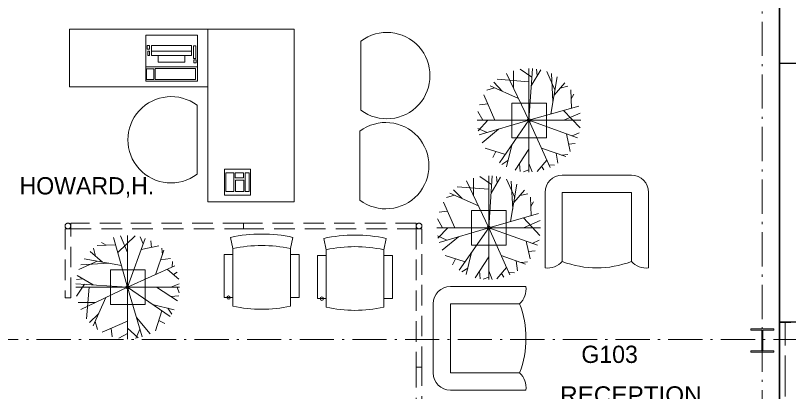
# Model space of a CAD drawing. Extents: x -118748 to -117136, y -118748 to -117596.
# Drawn here: x -117681.9 to -117467, y -118199.3 to -118094.8 of the extents above; entities that cross this region are included whole.
import ezdxf
from ezdxf.enums import TextEntityAlignment as Align

# ---------------------------------------------------------------- set-up
doc = ezdxf.new("R2010")
doc.units = 0
doc.header["$LTSCALE"] = 1.9
doc.header["$PDMODE"] = 32
doc.header["$PDSIZE"] = 0.95
for name, pattern in [('DOT_DASHED', [7.7, 5, -1.2, 0.3, -1.2]), ('LONG_DASHED', [7.5, 6, -1.5]), ('MEDIUM_DASHED', [4.5, 3, -1.5])]:
    doc.linetypes.add(name, pattern=pattern)
for name, color, linetype, lineweight in [('10', 7, 'DOT_DASHED', 13), ('12', 7, 'Continuous', 13), ('15', 7, 'Continuous', 13), ('16', 7, 'Continuous', 13), ('20', 7, 'MEDIUM_DASHED', 13), ('23', 7, 'Continuous', 25), ('30', 7, 'Continuous', 13), ('4', 7, 'Continuous', 35), ('5', 7, 'Continuous', 13), ('6', 7, 'Continuous', 13), ('60', 7, 'LONG_DASHED', 13), ('9', 7, 'Continuous', 35)]:
    doc.layers.add(name, color=color, linetype=linetype, lineweight=lineweight)
doc.layers.add('53', color=7, linetype='Continuous')

msp = doc.modelspace()

# ---------------------------------------------------------------- linework, layer by layer
at = {"layer": '10'}
for p, q in [((-117474.321, -117628.339), (-117474.321, -118698.41)), ((-118641.571, -118184.81), (-117285.521, -118184.81))]:
    msp.add_line(p, q, dxfattribs=at)
at = {"layer": '12'}
msp.add_lwpolyline([(-117477.504, -118188.362), (-117471.088, -118188.362), (-117471.088, -118187.966), (-117474.172, -118187.966), (-117474.172, -118182.262), (-117471.088, -118182.262), (-117471.088, -118181.866), (-117477.504, -118181.866), (-117477.504, -118182.262), (-117474.42, -118182.262), (-117474.42, -118187.966), (-117477.504, -118187.966)], close=True, dxfattribs=at)
at = {"layer": '15'}
for p, q in [((-117585.848, -118101.88), (-117585.848, -118121.08)), ((-117631.41, -118138.921), (-117631.41, -118119.721)), ((-117586.129, -118126.911), (-117586.129, -118146.111)), ((-117529.872, -118139.148), (-117510.672, -118139.148)), ((-117534.672, -118164.933), (-117534.672, -118143.948)), ((-117505.872, -118143.948), (-117505.872, -118164.933)), ((-117621.431, -118159.567), (-117622.107, -118156.439)), ((-117605.431, -118159.567), (-117604.755, -118156.439)), ((-117595.511, -118159.869), (-117596.187, -118156.741)), ((-117579.511, -118159.869), (-117578.835, -118156.741)), ((-117623.831, -118173.167), (-117623.831, -118161.167)), ((-117623.831, -118161.167), (-117621.431, -118161.167)), ((-117621.431, -118175.567), (-117621.431, -118159.567)), ((-117621.431, -118173.167), (-117621.431, -118161.167)), ((-117605.431, -118175.567), (-117605.431, -118159.567)), ((-117605.431, -118173.167), (-117605.431, -118161.167)), ((-117605.431, -118161.167), (-117603.031, -118161.167)), ((-117603.031, -118173.167), (-117603.031, -118161.167)), ((-117595.511, -118175.869), (-117595.511, -118159.869)), ((-117579.511, -118175.869), (-117579.511, -118159.869)), ((-117597.911, -118173.469), (-117597.911, -118161.469)), ((-117597.911, -118161.469), (-117595.511, -118161.469)), ((-117595.511, -118173.469), (-117595.511, -118161.469)), ((-117579.511, -118173.469), (-117579.511, -118161.469)), ((-117579.511, -118161.469), (-117577.111, -118161.469)), ((-117577.111, -118173.469), (-117577.111, -118161.469)), ((-117560.955, -118170.1), (-117539.969, -118170.1)), ((-117621.431, -118173.167), (-117623.831, -118173.167)), ((-117603.031, -118173.167), (-117605.431, -118173.167)), ((-117595.511, -118173.469), (-117597.911, -118173.469)), ((-117577.111, -118173.469), (-117579.511, -118173.469)), ((-117565.755, -118194.1), (-117565.755, -118174.899)), ((-117539.969, -118198.899), (-117560.955, -118198.899))]:
    msp.add_line(p, q, dxfattribs=at)
at = {"layer": '15', "lineweight": 25}
for p, q in [((-117469.521, -118108.01), (-117459.921, -118108.01)), ((-117469.521, -118180.01), (-117469.521, -118108.01)), ((-117379.921, -118180.01), (-117469.521, -118180.01))]:
    msp.add_line(p, q, dxfattribs=at)
at = {"layer": '15'}
for points in [[(-117628.41, -118114.556), (-117628.41, -118098.556), (-117666.81, -118098.556), (-117666.81, -118114.556)], [(-117604.41, -118146.556), (-117604.41, -118098.556), (-117628.41, -118098.556), (-117628.41, -118146.556)]]:
    msp.add_lwpolyline(points, close=True, dxfattribs=at)
for points in [[(-117529.872, -118163.148), (-117529.872, -118143.948), (-117510.672, -118143.948), (-117510.672, -118163.148)], [(-117541.755, -118194.1), (-117560.955, -118194.1), (-117560.955, -118174.899), (-117541.755, -118174.899)]]:
    msp.add_lwpolyline(points, dxfattribs=at)
for centre, radius, start, end in [((-117578.648, -118111.48), 12, 233.13011, 126.8699), ((-117638.61, -118129.321), 12, 53.1301, 306.8699), ((-117578.929, -118136.511), 12, 233.13011, 126.8699), ((-117529.872, -118143.948), 4.8, 90, 180), ((-117510.672, -118143.948), 4.8, 0, 90), ((-117613.431, -118196.575), 41.063, 77.80217, 102.19783), ((-117587.511, -118196.877), 41.063, 77.80217, 102.19783), ((-117613.431, -118196.575), 37.863, 77.80217, 102.19783), ((-117613.431, -118196.575), 37.863, 77.80217, 102.19783), ((-117587.511, -118196.877), 37.863, 77.80217, 102.19783), ((-117587.511, -118196.877), 37.863, 77.80217, 102.19783), ((-117533.977, -118159.456), 5.521, 262.77334, 318.03706), ((-117520.272, -118138.234), 26.699, 248.92678, 291.07322), ((-117506.566, -118159.456), 5.521, 221.96294, 277.22666), ((-117560.955, -118174.899), 4.8, 90, 180), ((-117545.447, -118170.794), 5.521, 311.96294, 7.22666), ((-117613.431, -118138.559), 37.863, 257.80217, 282.19782), ((-117587.511, -118138.86), 37.863, 257.80217, 282.19782), ((-117566.668, -118184.5), 26.699, 338.92678, 21.07322), ((-117560.955, -118194.1), 4.8, 180, 270), ((-117545.447, -118198.205), 5.521, 352.77334, 48.03706)]:
    msp.add_arc(centre, radius, start, end, dxfattribs=at)
for p in [(-117622.631, -118173.167), (-117596.711, -118173.469)]:
    msp.add_point(p, dxfattribs=at)
at = {"layer": '16'}
for p, q in [((-117469.521, -118108.01), (-117469.521, -118069.61)), ((-117631.259, -118109.006), (-117645.659, -118109.006))]:
    msp.add_line(p, q, dxfattribs=at)
for points in [[(-117631.259, -118113.006), (-117631.259, -118100.206), (-117645.659, -118100.206), (-117645.659, -118113.006)], [(-117644.657, -118103.104), (-117644.657, -118104.102), (-117645.239, -118104.102), (-117645.239, -118103.104)], [(-117632.924, -118104.685), (-117632.924, -118103.085), (-117644.033, -118103.085), (-117644.033, -118104.685)], [(-117631.717, -118106.724), (-117631.717, -118103.187), (-117632.424, -118103.187), (-117632.424, -118106.724)], [(-117644.657, -118104.685), (-117644.657, -118105.933), (-117645.073, -118105.933), (-117645.073, -118104.685)], [(-117632.924, -118105.891), (-117632.924, -118104.685), (-117644.033, -118104.685), (-117644.033, -118105.891)], [(-117634.837, -118107.764), (-117634.837, -118105.891), (-117642.16, -118105.891), (-117642.16, -118107.764)], [(-117631.634, -118107.972), (-117631.634, -118107.14), (-117632.299, -118107.14), (-117632.299, -118107.972)], [(-117643.408, -118109.636), (-117643.408, -118112.59), (-117645.406, -118112.59), (-117645.406, -118109.636)], [(-117631.8, -118109.553), (-117631.8, -118112.549), (-117642.992, -118112.549), (-117642.992, -118109.553)], [(-117616.563, -118144.712), (-117616.563, -118137.512), (-117623.763, -118137.512), (-117623.763, -118144.712)], [(-117621.182, -118138.547), (-117621.182, -118143.664), (-117623.387, -118143.664), (-117623.387, -118138.547)], [(-117618.519, -118138.464), (-117618.519, -118139.92), (-117620.807, -118139.92), (-117620.807, -118138.464)], [(-117618.02, -118143.706), (-117618.02, -118138.464), (-117616.938, -118138.464), (-117616.938, -118143.706)], [(-117618.436, -118140.585), (-117618.436, -118143.706), (-117620.724, -118143.706), (-117620.724, -118140.585)]]:
    msp.add_lwpolyline(points, close=True, dxfattribs=at)
at = {"layer": '20'}
for points in [[(-117618.495, -118154.079), (-117618.495, -118152.479), (-117666.495, -118152.479), (-117666.495, -118154.079)], [(-117570.495, -118154.079), (-117570.495, -118152.479), (-117618.495, -118152.479), (-117618.495, -118154.079)], [(-117666.495, -118154.079), (-117668.095, -118154.079), (-117668.095, -118173.279), (-117666.495, -118173.279)], [(-117570.495, -118192.479), (-117568.895, -118192.479), (-117568.895, -118154.079), (-117570.495, -118154.079)], [(-117570.495, -118240.479), (-117568.895, -118240.479), (-117568.895, -118192.479), (-117570.495, -118192.479)]]:
    msp.add_lwpolyline(points, close=True, dxfattribs=at)
for centre in [(-117667.295, -118153.279), (-117569.695, -118153.279)]:
    msp.add_circle(centre, 0.8, dxfattribs=at)
at = {"layer": '23'}
for p, q in [((-117469.521, -118180.01), (-117466.321, -118180.01)), ((-117469.521, -118292.01), (-117469.521, -118180.01))]:
    msp.add_line(p, q, dxfattribs=at)
at = {"layer": '30'}
for p, q in [((-117538.343, -118111.88), (-117541.613, -118109.705)), ((-117539.152, -118138.293), (-117539.152, -118109.493)), ((-117539.152, -118123.893), (-117538.184, -118109.526)), ((-117536.825, -118111.484), (-117536.998, -118109.655)), ((-117539.152, -118123.893), (-117545.335, -118110.888)), ((-117543.402, -118114.953), (-117543.399, -118110.134)), ((-117538.506, -118114.307), (-117535.866, -118109.873)), ((-117531.925, -118115.463), (-117534.189, -118110.375)), ((-117533.074, -118122.184), (-117531.303, -118111.82)), ((-117532.482, -118118.718), (-117532.899, -118110.921)), ((-117546.568, -118115.82), (-117548.935, -118113.326)), ((-117539.152, -118113.172), (-117547.947, -118112.491)), ((-117532.17, -118116.893), (-117529.212, -118113.474)), ((-117548.705, -118114.872), (-117550.877, -118115.533)), ((-117542.033, -118117.832), (-117549.921, -118114.333)), ((-117530.499, -118114.962), (-117528.293, -118114.436)), ((-117527.345, -118120.572), (-117527.528, -118115.393)), ((-117548.582, -118123.893), (-117551.677, -118116.788)), ((-117527.437, -118117.977), (-117526.695, -118116.668)), ((-117550.585, -118119.295), (-117552.903, -118119.62)), ((-117539.152, -118123.893), (-117525.29, -118119.994)), ((-117551.989, -118123.893), (-117553.344, -118121.455)), ((-117529.512, -118121.182), (-117524.912, -118126.036)), ((-117529.47, -118123.893), (-117524.892, -118121.892)), ((-117524.752, -118123.893), (-117553.552, -118123.893)), ((-117550.555, -118123.893), (-117553.255, -118126.801)), ((-117539.152, -118123.893), (-117552.96, -118127.979)), ((-117539.152, -118123.893), (-117547.332, -118135.744)), ((-117539.152, -118123.893), (-117533.25, -118137.028)), ((-117539.152, -118123.893), (-117525.605, -118128.777)), ((-117550.767, -118127.33), (-117553.375, -118126.144)), ((-117547.583, -118126.388), (-117552.117, -118130.158)), ((-117528.702, -118127.66), (-117527.667, -118132.579)), ((-117527.082, -118128.244), (-117525.173, -118127.352)), ((-117543.94, -118130.83), (-117545.402, -118136.866)), ((-117528.105, -118130.5), (-117526.272, -118130.333)), ((-117545.692, -118133.368), (-117551.302, -118131.622)), ((-117548.38, -118132.532), (-117549.209, -118134.198)), ((-117539.152, -118131.961), (-117542.944, -118137.785)), ((-117535.675, -118131.632), (-117528.898, -118134.004)), ((-117531.57, -118133.068), (-117531.148, -118135.864)), ((-117530.128, -118133.573), (-117528.328, -118133.391)), ((-117544.977, -118135.112), (-117546.639, -118136.194)), ((-117534.188, -118134.941), (-117536.871, -118138.111)), ((-117541.726, -118135.914), (-117541.548, -118138.092)), ((-117539.152, -118137.626), (-117540.667, -118138.213)), ((-117539.152, -118135.905), (-117538.215, -118138.263)), ((-117535.622, -118136.636), (-117534.991, -118137.679)), ((-117533.599, -118136.25), (-117532.015, -118136.4)), ((-117549.513, -118141.738), (-117552.783, -118139.563)), ((-117550.322, -118168.152), (-117550.322, -118139.352)), ((-117550.322, -118153.751), (-117549.354, -118139.384)), ((-117549.676, -118144.165), (-117547.036, -118139.731)), ((-117547.995, -118141.343), (-117548.168, -118139.514)), ((-117550.322, -118153.751), (-117556.505, -118140.746)), ((-117554.572, -118144.811), (-117554.569, -118139.992)), ((-117543.095, -118145.322), (-117545.359, -118140.234)), ((-117544.244, -118152.042), (-117542.473, -118141.679)), ((-117543.652, -118148.577), (-117544.069, -118140.78)), ((-117553.203, -118147.69), (-117561.091, -118144.191)), ((-117557.738, -118145.679), (-117560.105, -118143.185)), ((-117550.322, -118143.03), (-117559.117, -118142.35)), ((-117543.34, -118146.751), (-117540.382, -118143.333)), ((-117559.875, -118144.731), (-117562.047, -118145.392)), ((-117541.669, -118144.821), (-117539.463, -118144.295)), ((-117538.515, -118150.431), (-117538.698, -118145.252)), ((-117559.752, -118153.751), (-117562.847, -118146.647)), ((-117538.607, -118147.835), (-117537.865, -118146.527)), ((-117561.755, -118149.153), (-117564.073, -118149.479)), ((-117550.322, -118153.751), (-117536.46, -118149.853)), ((-117563.159, -118153.751), (-117564.514, -118151.313)), ((-117540.682, -118151.04), (-117536.082, -118155.895)), ((-117540.64, -118153.751), (-117536.062, -118151.75)), ((-117535.922, -118153.751), (-117564.722, -118153.751)), ((-117561.725, -118153.751), (-117564.425, -118156.659)), ((-117550.322, -118153.751), (-117564.13, -118157.838)), ((-117550.322, -118153.751), (-117558.502, -118165.602)), ((-117550.322, -118153.751), (-117544.42, -118166.887)), ((-117550.322, -118153.751), (-117536.775, -118158.635)), ((-117650.702, -118170.296), (-117654.6, -118156.434)), ((-117653.413, -118160.656), (-117648.558, -118156.056)), ((-117650.702, -118160.614), (-117652.703, -118156.036)), ((-117650.702, -118155.896), (-117650.702, -118184.696)), ((-117650.702, -118170.296), (-117645.818, -118156.75)), ((-117646.35, -118158.227), (-117647.243, -118156.318)), ((-117561.937, -118157.189), (-117564.545, -118156.003)), ((-117558.753, -118156.246), (-117563.287, -118160.017)), ((-117654.022, -118158.489), (-117659.201, -118158.672)), ((-117656.618, -118158.581), (-117657.926, -118157.84)), ((-117646.934, -118159.846), (-117642.015, -118158.811)), ((-117644.095, -118159.249), (-117644.262, -118157.416)), ((-117539.872, -118157.519), (-117538.837, -118162.438)), ((-117538.252, -118158.103), (-117536.343, -118157.21)), ((-117657.702, -118163.314), (-117661.12, -118160.356)), ((-117659.632, -118161.643), (-117660.159, -118159.437)), ((-117642.963, -118166.819), (-117640.591, -118160.042)), ((-117641.021, -118161.272), (-117641.204, -118159.472)), ((-117555.11, -118160.689), (-117556.572, -118166.724)), ((-117539.274, -118160.358), (-117537.442, -118160.191)), ((-117659.131, -118163.07), (-117664.219, -118165.333)), ((-117652.411, -118164.218), (-117662.774, -118162.447)), ((-117641.526, -118162.714), (-117638.731, -118162.292)), ((-117638.344, -118164.744), (-117638.194, -118163.159)), ((-117556.862, -118163.227), (-117562.472, -118161.48)), ((-117559.55, -118162.39), (-117560.379, -118164.057)), ((-117550.322, -118161.82), (-117554.114, -118167.643)), ((-117546.845, -118161.49), (-117540.068, -118163.862)), ((-117542.74, -118162.927), (-117542.318, -118165.722)), ((-117541.298, -118163.432), (-117539.498, -118163.249)), ((-117655.876, -118163.626), (-117663.673, -118164.044)), ((-117650.702, -118170.296), (-117637.567, -118164.394)), ((-117639.654, -118165.332), (-117636.483, -118168.015)), ((-117556.147, -118164.971), (-117557.809, -118166.052)), ((-117545.358, -118164.8), (-117548.041, -118167.97)), ((-117660.288, -118169.651), (-117664.722, -118167.01)), ((-117637.959, -118166.766), (-117636.916, -118166.136)), ((-117552.896, -118165.772), (-117552.718, -118167.951)), ((-117550.322, -118167.485), (-117551.837, -118168.072)), ((-117550.322, -118165.764), (-117549.385, -118168.121)), ((-117546.792, -118166.494), (-117546.161, -118167.537)), ((-117544.769, -118166.109), (-117543.185, -118166.259)), ((-117650.702, -118170.296), (-117665.069, -118169.329)), ((-117663.11, -118167.97), (-117664.94, -118168.142)), ((-117662.715, -118169.487), (-117664.89, -118172.757)), ((-117638.689, -118170.296), (-117636.332, -118169.36)), ((-117636.302, -118170.296), (-117665.102, -118170.296)), ((-117650.702, -118170.296), (-117663.707, -118176.479)), ((-117661.423, -118170.296), (-117662.103, -118179.092)), ((-117650.702, -118170.296), (-117646.615, -118184.104)), ((-117650.702, -118170.296), (-117638.851, -118178.476)), ((-117642.634, -118170.296), (-117636.81, -118174.088)), ((-117636.968, -118170.296), (-117636.381, -118171.811)), ((-117656.763, -118173.177), (-117660.262, -118181.065)), ((-117638.681, -118172.87), (-117636.502, -118172.692)), ((-117659.642, -118174.546), (-117664.461, -118174.543)), ((-117643.765, -118175.084), (-117637.729, -118176.546)), ((-117639.482, -118176.122), (-117638.401, -118177.783)), ((-117658.774, -118177.712), (-117661.268, -118180.079)), ((-117641.226, -118176.837), (-117642.973, -118182.446)), ((-117659.722, -118179.849), (-117659.061, -118182.021)), ((-117650.702, -118179.727), (-117657.806, -118182.821)), ((-117648.207, -118178.727), (-117644.436, -118183.262)), ((-117642.063, -118179.524), (-117640.396, -118180.354)), ((-117655.3, -118181.73), (-117654.974, -118184.048)), ((-117650.702, -118181.699), (-117647.794, -118184.399)), ((-117647.264, -118181.911), (-117648.45, -118184.519)), ((-117650.702, -118183.133), (-117653.14, -118184.488))]:
    msp.add_line(p, q, dxfattribs=at)
for points in [[(-117534.308, -118128.741), (-117534.308, -118119.141), (-117543.908, -118119.141), (-117543.908, -118128.741)], [(-117545.478, -118158.6), (-117545.478, -118149), (-117555.078, -118149), (-117555.078, -118158.6)], [(-117645.854, -118165.453), (-117655.454, -118165.453), (-117655.454, -118175.053), (-117645.854, -118175.053)]]:
    msp.add_lwpolyline(points, close=True, dxfattribs=at)
for p in [(-117539.152, -118123.893), (-117550.322, -118153.751), (-117650.702, -118170.296)]:
    msp.add_point(p, dxfattribs=at)
at = {"layer": '4'}
msp.add_lwpolyline([(-118496.721, -117964.01), (-118496.721, -118636.01), (-118271.121, -118636.01), (-118271.121, -118588.01), (-118115.969, -118588.01), (-118106.1, -118586.234), (-118096.66, -118581.314), (-118089.115, -118573.804), (-118084.156, -118564.399), (-118081.154, -118548.633), (-118079.134, -118548.633), (-117884.057, -118548.587), (-117881.646, -118565.336), (-117876.897, -118574.111), (-117869.271, -118581.538), (-117859.789, -118586.351), (-117850.271, -118588.01), (-117695.121, -118588.01), (-117695.121, -118636.01), (-117469.521, -118636.01), (-117469.521, -117964.01)], close=True, dxfattribs=at)
at = {"layer": '5'}
for points in [[(-117981.521, -118118.36), (-117981.521, -117964.01), (-117469.521, -117964.01), (-117469.521, -117992.81), (-117469.521, -118180.01), (-117469.521, -118292.01), (-117839.871, -118292.01), (-117839.871, -118184.81)], [(-117979.078, -117964.01), (-117469.521, -117964.01), (-117469.521, -118636.01), (-117695.121, -118636.01), (-117695.121, -118588.01), (-117850.271, -118588.01)]]:
    msp.add_lwpolyline(points, dxfattribs=at)
at = {"layer": '6'}
msp.add_lwpolyline([(-117981.521, -117964.01), (-117469.521, -117964.01), (-117469.521, -118292.01), (-117839.871, -118292.01), (-117839.871, -118184.81)], dxfattribs=at)
at = {"layer": '60'}
msp.add_line((-117467.921, -118343.21), (-117467.921, -118180.01), dxfattribs=at)

# ---------------------------------------------------------------- texts
at = {"layer": '53'}
msp.add_text('HOWARD,H.', height=4.8, dxfattribs=at).set_placement((-117680.729, -118144.507))
at = {"layer": '53', "width": 1.05}
msp.add_text('RECEPTION', height=4.8, dxfattribs=at).set_placement((-117530.466, -118202.638))
at = {"layer": '9'}
msp.add_text('G103', height=4.8, dxfattribs=at).set_placement((-117516.721, -118191.344), align=Align.CENTER)

doc.saveas('drawing.dxf')
